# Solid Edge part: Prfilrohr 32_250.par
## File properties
Username: ahadarics
Dokumentum tartalom típus: 0
Author: ahadarics
Last saved by: ahadarics
Revision: 85
Sűrűség: 0,000 kg/m^3
Pontosság: 0,990
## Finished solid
Body 1: solid body, 179 faces, 531 edges, 354 vertices.
  Faces by surface: cylinder 109, plane 70
  Edges by curve: line 313, circle 218
Bounding box of the edges (mm): 44.254 x 44.254 x 291.000, from (-22.1268, -22.1268, -13) to (22.1268, 22.1268, 278).
Cylindrical faces by radius (mm): R0.1 x16, R0.2 x30, R0.5 x32, R1 x6, R2.7 x8, R4.5 x4, R4.7 x4, R16 x1, R18 x8
Planar faces by outward normal: +x 6, +y 6, +z 1, -x 4, -y 4, -z 1, oblique 48
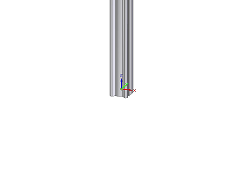
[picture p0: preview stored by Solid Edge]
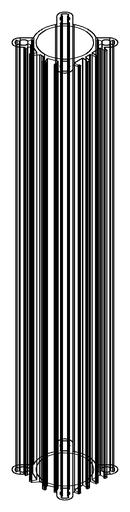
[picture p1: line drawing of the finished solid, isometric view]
